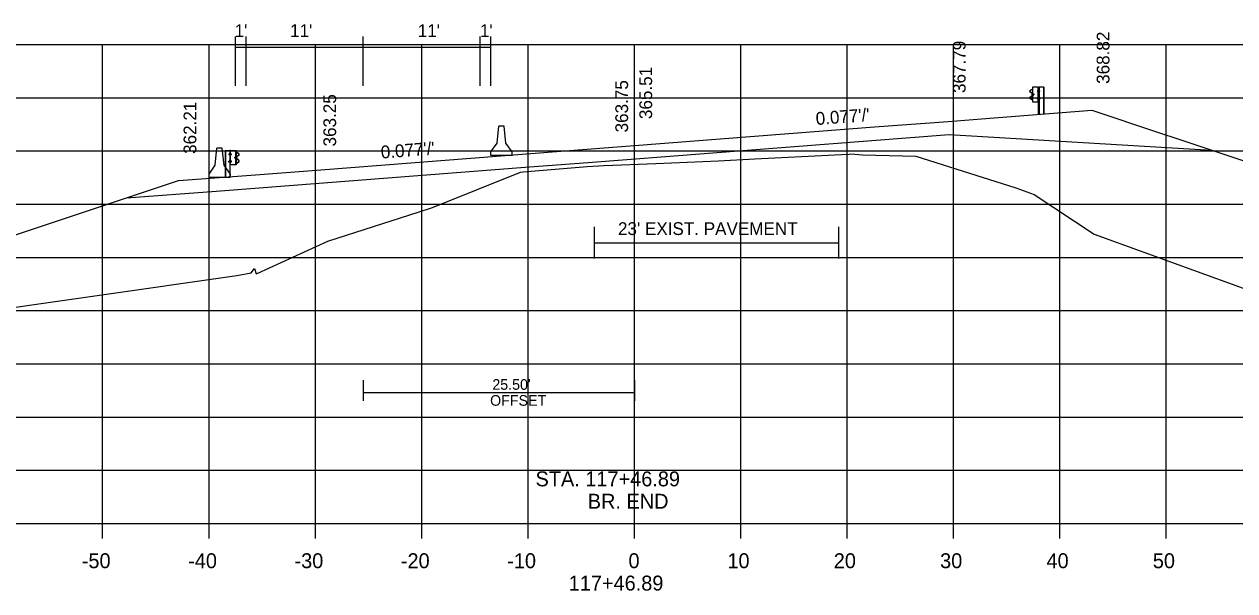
# Model space of a CAD drawing. Extents: x 1374859 to 1376773, y 382242 to 389804.
# Drawn here: x 1376077.2 to 1376191, y 383590.4 to 383643.7 of the extents above; entities that cross this region are included whole.
import ezdxf

# ---------------------------------------------------------------- set-up
doc = ezdxf.new("R2010")
doc.units = 0
for name, color, linetype in [('R_Axis', 7, 'Continuous'), ('R_Axis Annot', 7, 'Continuous'), ('R_Border Notes', 7, 'Continuous'), ('R_Draft', 7, 'Continuous'), ('R_Exist Surface', 7, 'Continuous'), ('R_Fin Surface', 7, 'Continuous'), ('R_Grid', 7, 'Continuous'), ('R_MOT', 7, 'Continuous'), ('R_Proposed Road', 7, 'Continuous'), ('R_Xsect Elev', 7, 'Continuous'), ('R_Xsect Slope', 7, 'Continuous')]:
    doc.layers.add(name, color=color, linetype=linetype)

msp = doc.modelspace()

# ---------------------------------------------------------------- linework, layer by layer
at = {"layer": 'R_Axis'}
for p, q in [((1375994.57, 383596.75), (1376274.57, 383596.75)), ((1376084.57, 383595.35), (1376084.57, 383596.75)), ((1376094.57, 383595.35), (1376094.57, 383596.75)), ((1376104.57, 383595.35), (1376104.57, 383596.75)), ((1376114.57, 383595.35), (1376114.57, 383596.75)), ((1376124.57, 383595.35), (1376124.57, 383596.75)), ((1376134.57, 383595.35), (1376134.57, 383596.75)), ((1376144.57, 383595.35), (1376144.57, 383596.75)), ((1376154.57, 383595.35), (1376154.57, 383596.75)), ((1376164.57, 383595.35), (1376164.57, 383596.75)), ((1376174.57, 383595.35), (1376174.57, 383596.75)), ((1376184.57, 383595.35), (1376184.57, 383596.75))]:
    msp.add_line(p, q, dxfattribs=at)
at = {"layer": 'R_Border Notes'}
for points in [[(1376130.77, 383624.63), (1376130.77, 383621.63)], [(1376153.75, 383624.63), (1376153.75, 383621.63)], [(1376130.77, 383623.13), (1376153.75, 383623.13)]]:
    msp.add_lwpolyline(points, dxfattribs=at)
at = {"layer": 'R_Exist Surface'}
msp.add_lwpolyline([(1376043.75, 383612.41), (1376097.19, 383620.06), (1376098.54, 383620.29), (1376098.84, 383620.7), (1376099, 383620.2), (1376099.15, 383620.27), (1376105.73, 383623.27), (1376114.33, 383626.04), (1376115.59, 383626.43), (1376123.85, 383629.74), (1376124.12, 383629.8), (1376130.13, 383630.28), (1376131.73, 383630.37), (1376136.59, 383630.58), (1376142.47, 383630.83), (1376145.88, 383631.01), (1376154.05, 383631.42), (1376154.77, 383631.46), (1376154.95, 383631.47), (1376156.02, 383631.38), (1376161.03, 383631.26), (1376170.43, 383628.29), (1376172.16, 383627.67), (1376177.8, 383623.92), (1376201.15, 383615.47)], dxfattribs=at)
at = {"layer": 'R_Fin Surface'}
for points in [[(1376021.3, 383605.53), (1376091.7, 383628.96), (1376098.93, 383629.52), (1376105.08, 383629.99), (1376127.64, 383631.73), (1376134.58, 383632.26), (1376157.14, 383634), (1376164.08, 383634.53), (1376167.2, 383634.77), (1376177.58, 383635.57), (1376183.84, 383633.48), (1376185.75, 383632.85), (1376192.14, 383630.72), (1376194.08, 383630.07), (1376215.8, 383622.83), (1376242.12, 383614.04), (1376244.24, 383613.34), (1376251.97, 383610.77), (1376254.66, 383611.67), (1376256.11, 383612.15)], [(1376086.8, 383627.33), (1376095.23, 383627.98), (1376124.71, 383630.25), (1376130.21, 383630.67), (1376164.17, 383633.29), (1376188.81, 383631.83)]]:
    msp.add_lwpolyline(points, dxfattribs=at)
at = {"layer": 'R_Grid'}
for p, q in [((1375994.57, 383641.75), (1376274.57, 383641.75)), ((1376084.57, 383596.75), (1376084.57, 383641.75)), ((1376094.57, 383596.75), (1376094.57, 383641.75)), ((1376104.57, 383596.75), (1376104.57, 383641.75)), ((1376114.57, 383596.75), (1376114.57, 383641.75)), ((1376124.57, 383596.75), (1376124.57, 383641.75)), ((1376134.57, 383596.75), (1376134.57, 383641.75)), ((1376144.57, 383596.75), (1376144.57, 383641.75)), ((1376154.57, 383596.75), (1376154.57, 383641.75)), ((1376164.57, 383596.75), (1376164.57, 383641.75)), ((1376174.57, 383596.75), (1376174.57, 383641.75)), ((1376184.57, 383596.75), (1376184.57, 383641.75)), ((1375994.57, 383636.75), (1376274.57, 383636.75)), ((1375994.57, 383631.75), (1376274.57, 383631.75)), ((1375994.57, 383626.75), (1376274.57, 383626.75)), ((1375994.57, 383621.75), (1376274.57, 383621.75)), ((1375994.57, 383616.75), (1376274.57, 383616.75)), ((1375994.57, 383611.75), (1376274.57, 383611.75)), ((1375994.57, 383606.75), (1376274.57, 383606.75)), ((1375994.57, 383601.75), (1376274.57, 383601.75)), ((1375994.57, 383596.75), (1376274.57, 383596.75))]:
    msp.add_line(p, q, dxfattribs=at)
at = {"layer": 'R_MOT'}
for p, q in [((1376097.07, 383637.86), (1376097.07, 383642.5)), ((1376098.07, 383637.86), (1376098.07, 383642.5)), ((1376109.07, 383637.86), (1376109.07, 383642.5)), ((1376120.07, 383637.86), (1376120.07, 383642.5)), ((1376121.07, 383637.86), (1376121.07, 383642.5)), ((1376097.07, 383641.5), (1376121.07, 383641.5)), ((1376121.65, 383632.49), (1376121.82, 383634.08)), ((1376122.07, 383634.08), (1376121.82, 383634.08)), ((1376122.32, 383634.08), (1376122.07, 383634.08)), ((1376122.49, 383632.49), (1376122.32, 383634.08)), ((1376121.08, 383631.66), (1376121.65, 383632.49)), ((1376123.08, 383631.66), (1376122.49, 383632.49)), ((1376095.15, 383630.42), (1376095.32, 383632)), ((1376095.57, 383632), (1376095.32, 383632)), ((1376095.82, 383632), (1376095.57, 383632)), ((1376095.99, 383630.41), (1376095.82, 383632)), ((1376121.07, 383631.33), (1376121.08, 383631.66)), ((1376123.07, 383631.33), (1376121.07, 383631.33)), ((1376123.07, 383631.33), (1376123.08, 383631.66)), ((1376094.58, 383629.58), (1376095.15, 383630.42)), ((1376096.58, 383629.58), (1376095.99, 383630.41)), ((1376094.57, 383629.25), (1376094.58, 383629.58)), ((1376096.57, 383629.25), (1376094.57, 383629.25)), ((1376096.57, 383629.25), (1376096.58, 383629.58)), ((1376109.07, 383610.21), (1376109.07, 383608.28)), ((1376134.57, 383610.21), (1376134.57, 383608.28)), ((1376134.57, 383609.03), (1376109.07, 383609.03))]:
    msp.add_line(p, q, dxfattribs=at)
at = {"layer": 'R_Proposed Road'}
for p, q in [((1376172.04, 383636.37), (1376172.04, 383637.73)), ((1376172.54, 383637.74), (1376172.54, 383637.74)), ((1376172.54, 383637.74), (1376172.61, 383637.74)), ((1376172.57, 383635.22), (1376172.57, 383637.74)), ((1376173.03, 383637.74), (1376173.03, 383635.22)), ((1376173.06, 383637.74), (1376173.06, 383635.22)), ((1376171.76, 383637.42), (1376171.89, 383637.52)), ((1376171.89, 383636.57), (1376171.76, 383636.68)), ((1376171.94, 383637.17), (1376171.77, 383637.28)), ((1376171.78, 383637.4), (1376171.91, 383637.51)), ((1376171.95, 383637.19), (1376171.78, 383637.3)), ((1376171.9, 383636.59), (1376171.78, 383636.7)), ((1376171.79, 383636.84), (1376171.94, 383636.94)), ((1376171.8, 383636.82), (1376171.96, 383636.92)), ((1376171.89, 383637.52), (1376172.01, 383637.58)), ((1376171.91, 383637.51), (1376172, 383637.56)), ((1376171.97, 383636.99), (1376171.97, 383637.12)), ((1376172, 383636.99), (1376172, 383637.12)), ((1376172.05, 383636.99), (1376172.05, 383637.12)), ((1376172.05, 383637.12), (1376172.1, 383637.12)), ((1376172.05, 383637.09), (1376172.1, 383637.09)), ((1376172.05, 383637.02), (1376172.09, 383637.02)), ((1376172.05, 383637.02), (1376172.1, 383637.02)), ((1376172.05, 383636.99), (1376172.1, 383636.99)), ((1376172.11, 383637.01), (1376172.11, 383637.1)), ((1376172.53, 383637.43), (1376172.48, 383637.43)), ((1376172.48, 383637.43), (1376172.48, 383637.31)), ((1376172.48, 383637.37), (1376172.54, 383637.37)), ((1376172.53, 383637.31), (1376172.48, 383637.31)), ((1376172.48, 383636.62), (1376172.48, 383636.75)), ((1376172.48, 383636.75), (1376172.53, 383636.75)), ((1376172.48, 383636.69), (1376172.54, 383636.69)), ((1376172.48, 383636.62), (1376172.53, 383636.62)), ((1376172.61, 383637.31), (1376172.61, 383637.44)), ((1376172.61, 383637.44), (1376172.65, 383637.44)), ((1376172.61, 383637.41), (1376172.66, 383637.41)), ((1376172.61, 383637.34), (1376172.65, 383637.34)), ((1376172.61, 383637.34), (1376172.66, 383637.34)), ((1376172.61, 383637.31), (1376172.66, 383637.31)), ((1376172.62, 383636.62), (1376172.62, 383636.75)), ((1376172.62, 383636.75), (1376172.67, 383636.75)), ((1376172.62, 383636.72), (1376172.67, 383636.72)), ((1376172.62, 383636.65), (1376172.66, 383636.65)), ((1376172.62, 383636.65), (1376172.67, 383636.65)), ((1376172.62, 383636.62), (1376172.67, 383636.62)), ((1376172.66, 383637.33), (1376172.66, 383637.42)), ((1376172.67, 383636.64), (1376172.67, 383636.73)), ((1376172, 383636.52), (1376171.89, 383636.57)), ((1376172.01, 383636.53), (1376171.9, 383636.59)), ((1376172.54, 383636.37), (1376172.57, 383636.37)), ((1376096.08, 383631.8), (1376096.08, 383629.28)), ((1376096.11, 383631.8), (1376096.11, 383629.28)), ((1376096.48, 383631.39), (1376096.48, 383631.48)), ((1376096.53, 383631.37), (1376096.48, 383631.37)), ((1376096.53, 383631.5), (1376096.49, 383631.5)), ((1376096.53, 383631.47), (1376096.49, 383631.47)), ((1376096.53, 383631.4), (1376096.49, 383631.4)), ((1376096.53, 383631.4), (1376096.49, 383631.4)), ((1376096.53, 383631.37), (1376096.53, 383631.5)), ((1376096.6, 383631.8), (1376096.54, 383631.8)), ((1376096.57, 383629.28), (1376096.57, 383631.8)), ((1376096.6, 383631.8), (1376096.6, 383631.8)), ((1376096.66, 383631.43), (1376096.6, 383631.43)), ((1376096.61, 383631.49), (1376096.66, 383631.49)), ((1376096.61, 383631.37), (1376096.66, 383631.37)), ((1376096.66, 383631.49), (1376096.66, 383631.37)), ((1376097.09, 383631.18), (1376097.04, 383631.18)), ((1376097.04, 383631.07), (1376097.04, 383631.16)), ((1376097.09, 383631.15), (1376097.04, 383631.15)), ((1376097.09, 383631.08), (1376097.04, 383631.08)), ((1376097.09, 383631.05), (1376097.04, 383631.05)), ((1376097.09, 383631.08), (1376097.05, 383631.08)), ((1376097.09, 383631.05), (1376097.09, 383631.18)), ((1376097.1, 383630.43), (1376097.1, 383631.79)), ((1376097.25, 383631.58), (1376097.14, 383631.64)), ((1376097.23, 383631.57), (1376097.14, 383631.62)), ((1376097.14, 383631.05), (1376097.14, 383631.18)), ((1376097.17, 383631.05), (1376097.17, 383631.18)), ((1376097.34, 383630.88), (1376097.18, 383630.98)), ((1376097.19, 383631.25), (1376097.36, 383631.36)), ((1376097.2, 383631.23), (1376097.37, 383631.34)), ((1376097.35, 383630.9), (1376097.2, 383631)), ((1376097.36, 383631.46), (1376097.23, 383631.57)), ((1376097.38, 383631.48), (1376097.25, 383631.58)), ((1376096.47, 383630.7), (1376096.47, 383630.79)), ((1376096.52, 383630.78), (1376096.47, 383630.78)), ((1376096.52, 383630.71), (1376096.47, 383630.71)), ((1376096.52, 383630.68), (1376096.47, 383630.68)), ((1376096.52, 383630.81), (1376096.48, 383630.81)), ((1376096.52, 383630.71), (1376096.48, 383630.71)), ((1376096.52, 383630.68), (1376096.52, 383630.81)), ((1376096.6, 383630.43), (1376096.57, 383630.43)), ((1376096.66, 383630.75), (1376096.6, 383630.75)), ((1376096.66, 383630.81), (1376096.61, 383630.81)), ((1376096.66, 383630.68), (1376096.61, 383630.68)), ((1376096.66, 383630.68), (1376096.66, 383630.81)), ((1376097.13, 383630.59), (1376097.24, 383630.65)), ((1376097.14, 383630.58), (1376097.25, 383630.63)), ((1376097.24, 383630.65), (1376097.37, 383630.76)), ((1376097.25, 383630.63), (1376097.38, 383630.74))]:
    msp.add_line(p, q, dxfattribs=at)
for points in [[(1376172.01, 383637.74), (1376172.01, 383636.37), (1376172.54, 383636.37), (1376172.54, 383637.74)], [(1376172.05, 383637.14), (1376172.05, 383636.97), (1376172.04, 383636.97), (1376172.04, 383637.14)], [(1376172.11, 383637.09), (1376172.11, 383637.02), (1376172.13, 383637.02), (1376172.13, 383637.09)], [(1376172.48, 383637.43), (1376172.48, 383637.31), (1376172.54, 383637.31), (1376172.54, 383637.43)], [(1376172.48, 383636.75), (1376172.48, 383636.62), (1376172.54, 383636.62), (1376172.54, 383636.75)], [(1376172.61, 383637.46), (1376172.61, 383637.29), (1376172.6, 383637.29), (1376172.6, 383637.46)], [(1376172.62, 383636.77), (1376172.62, 383636.6), (1376172.61, 383636.6), (1376172.61, 383636.77)], [(1376172.66, 383637.41), (1376172.66, 383637.34), (1376172.69, 383637.34), (1376172.69, 383637.41)], [(1376172.67, 383636.72), (1376172.67, 383636.65), (1376172.7, 383636.65), (1376172.7, 383636.72)], [(1376096.48, 383631.47), (1376096.48, 383631.4), (1376096.45, 383631.4), (1376096.45, 383631.47)], [(1376096.53, 383631.52), (1376096.53, 383631.35), (1376096.54, 383631.35), (1376096.54, 383631.52)], [(1376097.13, 383631.8), (1376097.13, 383630.43), (1376096.6, 383630.43), (1376096.6, 383631.8)], [(1376096.66, 383631.49), (1376096.66, 383631.37), (1376096.6, 383631.37), (1376096.6, 383631.49)], [(1376097.03, 383631.15), (1376097.03, 383631.08), (1376097.01, 383631.08), (1376097.01, 383631.15)], [(1376097.09, 383631.2), (1376097.09, 383631.03), (1376097.1, 383631.03), (1376097.1, 383631.2)], [(1376096.47, 383630.78), (1376096.47, 383630.71), (1376096.44, 383630.71), (1376096.44, 383630.78)], [(1376096.52, 383630.83), (1376096.52, 383630.66), (1376096.53, 383630.66), (1376096.53, 383630.83)], [(1376096.66, 383630.81), (1376096.66, 383630.68), (1376096.6, 383630.68), (1376096.6, 383630.81)]]:
    msp.add_lwpolyline(points, close=True, dxfattribs=at)
for points in [[(1376173.06, 383637.74), (1376172.61, 383637.74), (1376172.61, 383635.22)], [(1376096.08, 383631.8), (1376096.54, 383631.8), (1376096.53, 383629.28)]]:
    msp.add_lwpolyline(points, dxfattribs=at)
for centre, radius, start, end in [((1376171.81, 383637.35), 0.0856, 122.0217, 240.7501), ((1376171.85, 383636.75), 0.109, 120.88, 214.7816), ((1376171.81, 383637.35), 0.062, 122.0217, 240.7501), ((1376171.85, 383636.75), 0.0854, 120.88, 214.7816), ((1376171.98, 383637.05), 0.0453, 93.9303, 257.0446), ((1376171.91, 383637.12), 0.0622, 4.9556, 61.894), ((1376171.91, 383637.12), 0.0865, 4.9556, 61.894), ((1376171.93, 383636.98), 0.0462, 293.1464, 8.2196), ((1376171.93, 383636.98), 0.0703, 293.1464, 8.2196), ((1376172.08, 383637.1), 0.022, 317.7756, 45.4255), ((1376172.01, 383637.05), 0.0922, 339.7423, 20.2577), ((1376172.08, 383637.01), 0.025, 323.3766, 39.0666), ((1376172.64, 383637.42), 0.022, 317.7756, 45.4255), ((1376172.57, 383637.37), 0.0922, 339.7423, 20.2577), ((1376172.64, 383637.33), 0.025, 323.3766, 39.0666), ((1376172.65, 383636.73), 0.022, 317.7756, 45.4255), ((1376172.58, 383636.69), 0.0922, 339.7423, 20.2577), ((1376172.65, 383636.64), 0.025, 323.3766, 39.0666), ((1376096.5, 383631.48), 0.022, 134.5745, 222.2244), ((1376096.57, 383631.44), 0.0922, 159.7423, 200.2577), ((1376096.5, 383631.39), 0.025, 140.9334, 216.6234), ((1376097.06, 383631.16), 0.022, 134.5745, 222.2244), ((1376097.13, 383631.11), 0.0922, 159.7423, 200.2577), ((1376097.06, 383631.07), 0.025, 140.9334, 216.6234), ((1376097.23, 383631.18), 0.0865, 118.106, 175.0444), ((1376097.21, 383631.04), 0.0703, 171.7804, 246.8536), ((1376097.16, 383631.11), 0.0453, 282.9554, 86.0697), ((1376097.23, 383631.18), 0.0622, 118.106, 175.0444), ((1376097.21, 383631.04), 0.0462, 171.7804, 246.8536), ((1376097.3, 383630.81), 0.109, 325.2184, 59.12), ((1376097.33, 383631.41), 0.062, 299.2499, 57.9783), ((1376097.33, 383631.41), 0.0856, 299.2499, 57.9783), ((1376096.49, 383630.79), 0.022, 134.5745, 222.2244), ((1376096.56, 383630.75), 0.0922, 159.7423, 200.2577), ((1376096.49, 383630.7), 0.025, 140.9334, 216.6234), ((1376097.3, 383630.81), 0.0854, 325.2184, 59.12)]:
    msp.add_arc(centre, radius, start, end, dxfattribs=at)

# ---------------------------------------------------------------- texts
at = {"layer": 'R_Axis Annot'}
for s, p in [('-50', (1376082.61, 383592.55)), ('-40', (1376092.61, 383592.55)), ('-30', (1376102.61, 383592.55)), ('-20', (1376112.61, 383592.55)), ('-10', (1376122.61, 383592.55)), ('0', (1376134.01, 383592.55)), ('10', (1376143.31, 383592.55)), ('20', (1376153.31, 383592.55)), ('30', (1376163.31, 383592.55)), ('40', (1376173.31, 383592.55)), ('50', (1376183.31, 383592.55)), ('117+46.89', (1376128.39, 383590.45))]:
    msp.add_text(s, height=1.4, dxfattribs=at).set_placement(p)
at = {"layer": 'R_Border Notes'}
msp.add_text("23' EXIST. PAVEMENT", height=1.2, rotation=0, dxfattribs=at).set_placement((1376133.02, 383623.85))
for s, p in [('STA. 117+46.89', (1376125.27, 383600.24)), ('BR. END', (1376130.18, 383598.14))]:
    msp.add_text(s, height=1.4, dxfattribs=at).set_placement(p)
at = {"layer": 'R_Draft'}
for s, p in [("25.50'", (1376121.21, 383609.31)), ('OFFSET', (1376121, 383607.81))]:
    msp.add_text(s, height=1, dxfattribs=at).set_placement(p)
at = {"layer": 'R_MOT'}
for s, p in [("1'", (1376096.98, 383642.45)), ("11'", (1376102.19, 383642.45)), ("11'", (1376114.2, 383642.45)), ("1'", (1376120.04, 383642.45))]:
    msp.add_text(s, height=1.2, dxfattribs=at).set_placement(p)
at = {"layer": 'R_Xsect Elev'}
for s, p in [('368.82', (1376179.23, 383638.05)), ('367.79', (1376165.71, 383637.19)), ('365.51', (1376136.23, 383634.74)), ('363.75', (1376133.97, 383633.49)), ('363.25', (1376106.52, 383632.17)), ('362.21', (1376093.38, 383631.47))]:
    msp.add_text(s, height=1.2, rotation=90, dxfattribs=at).set_placement(p)
at = {"layer": 'R_Xsect Slope'}
for p in [(1376151.66, 383634.18), (1376110.77, 383631.03)]:
    msp.add_text("0.077'/'", height=1.2, rotation=4.4031, dxfattribs=at).set_placement(p)

doc.saveas('drawing.dxf')
